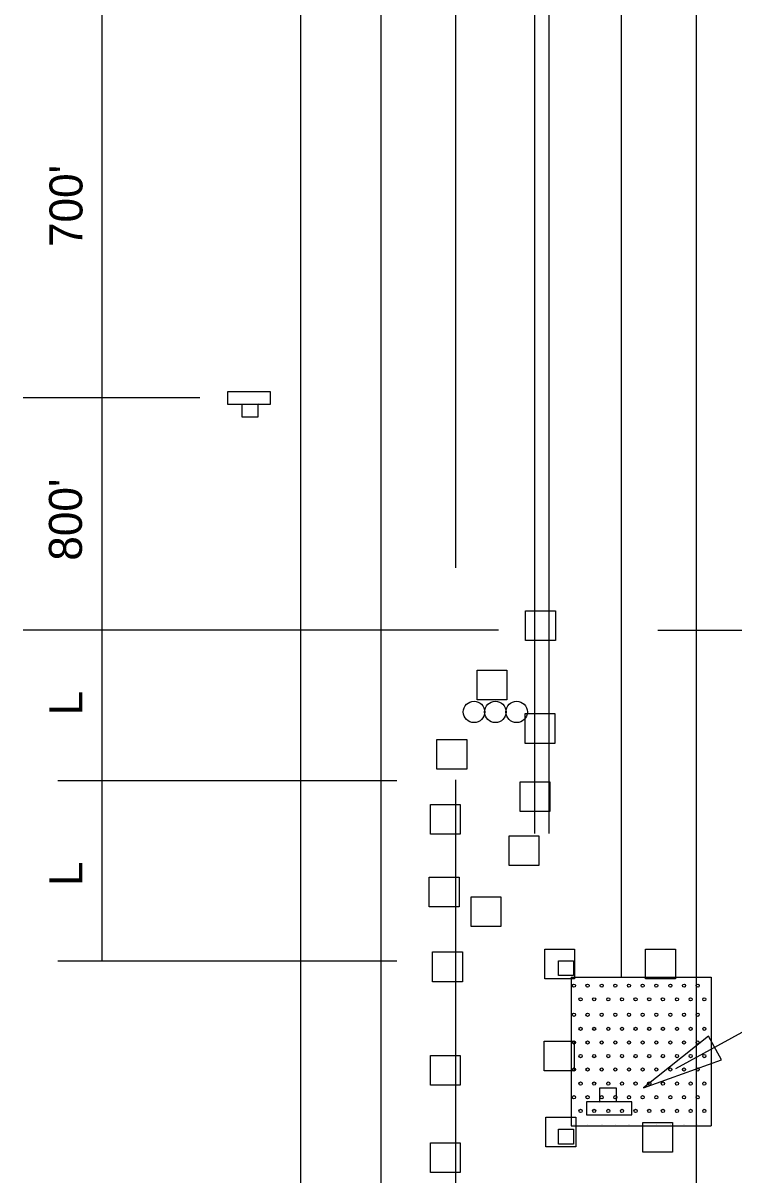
# Model space of a CAD drawing. Extents: x 15312.2 to 15319.5, y 15309 to 15319.2.
# Drawn here: x 15314.808 to 15316.1, y 15314.978 to 15317.071 of the extents above; entities that cross this region are included whole.
import ezdxf

# ---------------------------------------------------------------- set-up
doc = ezdxf.new("R2010")
doc.units = 0
for name, color, linetype in [('DETL-DIMS', 7, 'Continuous'), ('DETL-LINE', 7, 'Continuous'), ('DETL-NOTE', 7, 'Continuous'), ('USER-BORD', 7, 'Continuous')]:
    doc.layers.add(name, color=color, linetype=linetype)

# ---------------------------------------------------------------- blocks, each defined once
blk = doc.blocks.new('CD1')
at = {"layer": 'USER-BORD'}
blk.add_lwpolyline([(0, 0.031), (0.031, 0.031), (0.031, 0), (0, 0)], close=True, dxfattribs=at)
blk = doc.blocks.new('PANEL0')
at = {"layer": 'USER-BORD'}
for centre in [(0.0309, -0.0012), (0.0928, -0.0012), (0.1546, -0.0012)]:
    blk.add_circle(centre, 0.0312, dxfattribs=at)
blk = doc.blocks.new('SIGN13')
at = {"layer": 'USER-BORD'}
for points in [[(-0.013, 0.018), (0.011, 0.019), (0.011, 0.037), (-0.013, 0.037)], [(-0.031, 0.018), (-0.031, 0), (0.032, 0), (0.032, 0.018)]]:
    blk.add_lwpolyline(points, close=True, dxfattribs=at)

msp = doc.modelspace()

# ---------------------------------------------------------------- linework, layer by layer
at = {"layer": 'DETL-DIMS'}
for p, q in [((15314.952, 15316.7603), (15314.952, 15317.1273)), ((15314.952, 15316.3503), (15314.952, 15316.7603)), ((15315.129, 15316.39), (15314.808, 15316.39)), ((15314.952, 15315.9683), (15314.952, 15316.3503)), ((15315.672, 15315.968), (15314.808, 15315.968)), ((15314.952, 15315.3663), (15314.952, 15315.9683)), ((15315.961, 15315.968), (15316.476, 15315.968)), ((15315.487, 15315.694), (15314.871, 15315.694)), ((15315.994, 15315.171), (15316.454, 15315.425)), ((15315.487, 15315.366), (15314.871, 15315.366))]:
    msp.add_line(p, q, dxfattribs=at)
msp.add_lwpolyline([(15316.077, 15315.187), (15316.053, 15315.23), (15315.935, 15315.136)], close=True, dxfattribs=at)
at = {"layer": 'DETL-LINE'}
for p, q in [((15315.312, 15318.785), (15315.312, 15310.694)), ((15315.458, 15318.785), (15315.458, 15310.694)), ((15315.594, 15316.081), (15315.594, 15318.785)), ((15315.737, 15318.785), (15315.737, 15315.598)), ((15315.763, 15318.785), (15315.763, 15315.598)), ((15315.895, 15315.337), (15315.895, 15318.785)), ((15316.031, 15318.785), (15316.031, 15314.788)), ((15315.594, 15310.694), (15315.594, 15315.696)), ((15315.804, 15315.337), (15316.058, 15315.337)), ((15315.804, 15315.337), (15315.804, 15315.067)), ((15315.804, 15315.337), (15316.058, 15315.337)), ((15315.804, 15315.337), (15315.804, 15315.067)), ((15316.058, 15315.337), (15316.058, 15315.067)), ((15316.058, 15315.337), (15316.058, 15315.067)), ((15315.808, 15315.321), (15315.808, 15315.321)), ((15315.809, 15315.321), (15315.809, 15315.321)), ((15315.834, 15315.321), (15315.834, 15315.321)), ((15315.834, 15315.321), (15315.834, 15315.321)), ((15315.859, 15315.321), (15315.859, 15315.321)), ((15315.86, 15315.321), (15315.86, 15315.321)), ((15315.884, 15315.321), (15315.884, 15315.321)), ((15315.884, 15315.321), (15315.884, 15315.321)), ((15315.908, 15315.321), (15315.908, 15315.321)), ((15315.909, 15315.321), (15315.909, 15315.321)), ((15315.934, 15315.321), (15315.934, 15315.321)), ((15315.934, 15315.321), (15315.934, 15315.321)), ((15315.959, 15315.321), (15315.959, 15315.321)), ((15315.959, 15315.321), (15315.959, 15315.321)), ((15315.984, 15315.321), (15315.984, 15315.321)), ((15315.984, 15315.321), (15315.984, 15315.321)), ((15316.008, 15315.321), (15316.008, 15315.321)), ((15316.009, 15315.321), (15316.009, 15315.321)), ((15316.034, 15315.321), (15316.034, 15315.321)), ((15316.034, 15315.321), (15316.034, 15315.321)), ((15315.821, 15315.297), (15315.821, 15315.297)), ((15315.821, 15315.297), (15315.821, 15315.297)), ((15315.846, 15315.297), (15315.846, 15315.297)), ((15315.846, 15315.297), (15315.846, 15315.297)), ((15315.872, 15315.297), (15315.872, 15315.297)), ((15315.872, 15315.297), (15315.872, 15315.297)), ((15315.896, 15315.297), (15315.896, 15315.297)), ((15315.896, 15315.297), (15315.896, 15315.297)), ((15315.921, 15315.297), (15315.921, 15315.297)), ((15315.921, 15315.297), (15315.921, 15315.297)), ((15315.946, 15315.297), (15315.946, 15315.297)), ((15315.946, 15315.297), (15315.946, 15315.297)), ((15315.971, 15315.297), (15315.971, 15315.297)), ((15315.971, 15315.297), (15315.971, 15315.297)), ((15315.996, 15315.297), (15315.996, 15315.297)), ((15315.996, 15315.297), (15315.996, 15315.297)), ((15316.021, 15315.297), (15316.021, 15315.297)), ((15316.021, 15315.297), (15316.021, 15315.297)), ((15316.046, 15315.297), (15316.046, 15315.297)), ((15316.046, 15315.297), (15316.046, 15315.297)), ((15315.808, 15315.269), (15315.808, 15315.269)), ((15315.809, 15315.269), (15315.809, 15315.269)), ((15315.834, 15315.269), (15315.834, 15315.269)), ((15315.834, 15315.269), (15315.834, 15315.269)), ((15315.859, 15315.269), (15315.859, 15315.269)), ((15315.86, 15315.269), (15315.86, 15315.269)), ((15315.884, 15315.269), (15315.884, 15315.269)), ((15315.884, 15315.269), (15315.884, 15315.269)), ((15315.908, 15315.269), (15315.908, 15315.269)), ((15315.909, 15315.269), (15315.909, 15315.269)), ((15315.934, 15315.269), (15315.934, 15315.269)), ((15315.934, 15315.269), (15315.934, 15315.269)), ((15315.959, 15315.269), (15315.959, 15315.269)), ((15315.959, 15315.269), (15315.959, 15315.269)), ((15315.984, 15315.269), (15315.984, 15315.269)), ((15315.984, 15315.269), (15315.984, 15315.269)), ((15316.008, 15315.269), (15316.008, 15315.269)), ((15316.009, 15315.269), (15316.009, 15315.269)), ((15316.034, 15315.269), (15316.034, 15315.269)), ((15316.034, 15315.269), (15316.034, 15315.269)), ((15315.821, 15315.243), (15315.821, 15315.243)), ((15315.846, 15315.243), (15315.846, 15315.243)), ((15315.872, 15315.243), (15315.872, 15315.243)), ((15315.896, 15315.243), (15315.896, 15315.243)), ((15315.921, 15315.243), (15315.921, 15315.243)), ((15315.946, 15315.243), (15315.946, 15315.243)), ((15315.971, 15315.243), (15315.971, 15315.243)), ((15315.996, 15315.243), (15315.996, 15315.243)), ((15316.021, 15315.243), (15316.021, 15315.243)), ((15316.046, 15315.243), (15316.046, 15315.243)), ((15315.808, 15315.218), (15315.808, 15315.218)), ((15315.809, 15315.218), (15315.809, 15315.218)), ((15315.834, 15315.218), (15315.834, 15315.218)), ((15315.834, 15315.218), (15315.834, 15315.218)), ((15315.859, 15315.218), (15315.859, 15315.218)), ((15315.86, 15315.218), (15315.86, 15315.218)), ((15315.884, 15315.218), (15315.884, 15315.218)), ((15315.884, 15315.218), (15315.884, 15315.218)), ((15315.908, 15315.218), (15315.908, 15315.218)), ((15315.909, 15315.218), (15315.909, 15315.218)), ((15315.934, 15315.218), (15315.934, 15315.218)), ((15315.934, 15315.218), (15315.934, 15315.218)), ((15315.959, 15315.218), (15315.959, 15315.218)), ((15315.959, 15315.218), (15315.959, 15315.218)), ((15315.984, 15315.218), (15315.984, 15315.218)), ((15315.984, 15315.218), (15315.984, 15315.218)), ((15316.008, 15315.218), (15316.008, 15315.218)), ((15316.009, 15315.218), (15316.009, 15315.218)), ((15316.034, 15315.218), (15316.034, 15315.218)), ((15316.034, 15315.218), (15316.034, 15315.218)), ((15315.821, 15315.193), (15315.821, 15315.193)), ((15315.821, 15315.193), (15315.821, 15315.193)), ((15315.846, 15315.193), (15315.846, 15315.193)), ((15315.846, 15315.193), (15315.846, 15315.193)), ((15315.872, 15315.193), (15315.872, 15315.193)), ((15315.872, 15315.193), (15315.872, 15315.193)), ((15315.896, 15315.193), (15315.896, 15315.193)), ((15315.896, 15315.193), (15315.896, 15315.193)), ((15315.921, 15315.193), (15315.921, 15315.193)), ((15315.921, 15315.193), (15315.921, 15315.193)), ((15315.946, 15315.193), (15315.946, 15315.193)), ((15315.946, 15315.193), (15315.946, 15315.193)), ((15315.971, 15315.193), (15315.971, 15315.193)), ((15315.971, 15315.193), (15315.971, 15315.193)), ((15315.996, 15315.193), (15315.996, 15315.193)), ((15315.996, 15315.193), (15315.996, 15315.193)), ((15316.021, 15315.193), (15316.021, 15315.193)), ((15316.021, 15315.193), (15316.021, 15315.193)), ((15316.046, 15315.193), (15316.046, 15315.193)), ((15316.046, 15315.193), (15316.046, 15315.193)), ((15315.808, 15315.169), (15315.808, 15315.169)), ((15315.809, 15315.169), (15315.809, 15315.169)), ((15315.834, 15315.169), (15315.834, 15315.169)), ((15315.834, 15315.169), (15315.834, 15315.169)), ((15315.859, 15315.169), (15315.859, 15315.169)), ((15315.86, 15315.169), (15315.86, 15315.169)), ((15315.884, 15315.169), (15315.884, 15315.169)), ((15315.884, 15315.169), (15315.884, 15315.169)), ((15315.908, 15315.169), (15315.908, 15315.169)), ((15315.909, 15315.169), (15315.909, 15315.169)), ((15315.934, 15315.169), (15315.934, 15315.169)), ((15315.934, 15315.169), (15315.934, 15315.169)), ((15315.959, 15315.169), (15315.959, 15315.169)), ((15315.959, 15315.169), (15315.959, 15315.169)), ((15315.984, 15315.169), (15315.984, 15315.169)), ((15315.984, 15315.169), (15315.984, 15315.169)), ((15316.008, 15315.169), (15316.008, 15315.169)), ((15316.009, 15315.169), (15316.009, 15315.169)), ((15316.034, 15315.169), (15316.034, 15315.169)), ((15316.034, 15315.169), (15316.034, 15315.169)), ((15315.821, 15315.144), (15315.821, 15315.144)), ((15315.846, 15315.144), (15315.846, 15315.144)), ((15315.872, 15315.144), (15315.872, 15315.144)), ((15315.896, 15315.144), (15315.896, 15315.144)), ((15315.921, 15315.144), (15315.921, 15315.144)), ((15315.946, 15315.144), (15315.946, 15315.144)), ((15315.971, 15315.144), (15315.971, 15315.144)), ((15315.996, 15315.144), (15315.996, 15315.144)), ((15316.021, 15315.144), (15316.021, 15315.144)), ((15316.046, 15315.144), (15316.046, 15315.144)), ((15315.808, 15315.119), (15315.808, 15315.119)), ((15315.809, 15315.119), (15315.809, 15315.119)), ((15315.834, 15315.119), (15315.834, 15315.119)), ((15315.834, 15315.119), (15315.834, 15315.119)), ((15315.859, 15315.119), (15315.859, 15315.119)), ((15315.86, 15315.119), (15315.86, 15315.119)), ((15315.884, 15315.119), (15315.884, 15315.119)), ((15315.884, 15315.119), (15315.884, 15315.119)), ((15315.908, 15315.119), (15315.908, 15315.119)), ((15315.909, 15315.119), (15315.909, 15315.119)), ((15315.934, 15315.119), (15315.934, 15315.119)), ((15315.934, 15315.119), (15315.934, 15315.119)), ((15315.959, 15315.119), (15315.959, 15315.119)), ((15315.959, 15315.119), (15315.959, 15315.119)), ((15315.984, 15315.119), (15315.984, 15315.119)), ((15315.984, 15315.119), (15315.984, 15315.119)), ((15316.008, 15315.119), (15316.008, 15315.119)), ((15316.009, 15315.119), (15316.009, 15315.119)), ((15316.034, 15315.119), (15316.034, 15315.119)), ((15316.034, 15315.119), (15316.034, 15315.119)), ((15315.821, 15315.094), (15315.821, 15315.094)), ((15315.821, 15315.094), (15315.821, 15315.094)), ((15315.846, 15315.094), (15315.846, 15315.094)), ((15315.846, 15315.094), (15315.846, 15315.094)), ((15315.872, 15315.094), (15315.872, 15315.094)), ((15315.872, 15315.094), (15315.872, 15315.094)), ((15315.896, 15315.094), (15315.896, 15315.094)), ((15315.896, 15315.094), (15315.896, 15315.094)), ((15315.921, 15315.094), (15315.921, 15315.094)), ((15315.921, 15315.094), (15315.921, 15315.094)), ((15315.946, 15315.094), (15315.946, 15315.094)), ((15315.946, 15315.094), (15315.946, 15315.094)), ((15315.971, 15315.094), (15315.971, 15315.094)), ((15315.971, 15315.094), (15315.971, 15315.094)), ((15315.996, 15315.094), (15315.996, 15315.094)), ((15315.996, 15315.094), (15315.996, 15315.094)), ((15316.021, 15315.094), (15316.021, 15315.094)), ((15316.021, 15315.094), (15316.021, 15315.094)), ((15316.046, 15315.094), (15316.046, 15315.094)), ((15316.046, 15315.094), (15316.046, 15315.094)), ((15315.804, 15315.067), (15316.058, 15315.067)), ((15315.804, 15315.067), (15316.058, 15315.067)), ((15315.808, 15315.069), (15315.808, 15315.069)), ((15315.809, 15315.069), (15315.809, 15315.069)), ((15315.834, 15315.069), (15315.834, 15315.069)), ((15315.834, 15315.069), (15315.834, 15315.069)), ((15315.859, 15315.069), (15315.859, 15315.069)), ((15315.86, 15315.069), (15315.86, 15315.069)), ((15315.884, 15315.069), (15315.884, 15315.069)), ((15315.884, 15315.069), (15315.884, 15315.069)), ((15315.908, 15315.069), (15315.908, 15315.069)), ((15315.909, 15315.069), (15315.909, 15315.069)), ((15315.934, 15315.069), (15315.934, 15315.069)), ((15315.934, 15315.069), (15315.934, 15315.069)), ((15315.959, 15315.069), (15315.959, 15315.069)), ((15315.959, 15315.069), (15315.959, 15315.069)), ((15315.984, 15315.069), (15315.984, 15315.069)), ((15315.984, 15315.069), (15315.984, 15315.069)), ((15316.008, 15315.069), (15316.008, 15315.069)), ((15316.009, 15315.069), (15316.009, 15315.069)), ((15316.034, 15315.069), (15316.034, 15315.069)), ((15316.034, 15315.069), (15316.034, 15315.069))]:
    msp.add_line(p, q, dxfattribs=at)
for points in [[(15315.895, 15317.017), (15315.895, 15317.047)], [(15315.594, 15316.981), (15315.594, 15317.019)], [(15315.895, 15316.987), (15315.895, 15317.017)], [(15315.594, 15316.943), (15315.594, 15316.981)], [(15315.895, 15316.777), (15315.895, 15316.807)], [(15315.895, 15316.747), (15315.895, 15316.777)], [(15315.594, 15316.681), (15315.594, 15316.719)], [(15315.594, 15316.643), (15315.594, 15316.681)], [(15315.895, 15316.537), (15315.895, 15316.567)], [(15315.895, 15316.507), (15315.895, 15316.537)], [(15315.594, 15316.381), (15315.594, 15316.419)], [(15315.594, 15316.343), (15315.594, 15316.381)], [(15315.895, 15316.297), (15315.895, 15316.327)], [(15315.895, 15316.267), (15315.895, 15316.297)], [(15315.594, 15316.081), (15315.594, 15316.119)], [(15315.895, 15316.057), (15315.895, 15316.087)], [(15315.895, 15316.027), (15315.895, 15316.057)], [(15315.895, 15315.817), (15315.895, 15315.847)], [(15315.895, 15315.787), (15315.895, 15315.817)], [(15315.895, 15315.577), (15315.895, 15315.607)], [(15315.895, 15315.547), (15315.895, 15315.577)], [(15315.594, 15315.494), (15315.594, 15315.524)], [(15315.594, 15315.464), (15315.594, 15315.494)], [(15315.895, 15315.337), (15315.895, 15315.367)], [(15315.594, 15315.254), (15315.594, 15315.284)], [(15315.594, 15315.224), (15315.594, 15315.254)], [(15315.594, 15315.014), (15315.594, 15315.044)], [(15315.594, 15314.984), (15315.594, 15315.014)]]:
    msp.add_lwpolyline(points, dxfattribs=at)
for centre in [(15315.8088, 15315.3218), (15315.8336, 15315.3218), (15315.8592, 15315.3218), (15315.884, 15315.3218), (15315.9088, 15315.3218), (15315.9336, 15315.3218), (15315.9584, 15315.3218), (15315.984, 15315.3218), (15316.0088, 15315.3218), (15316.0336, 15315.3218), (15315.8208, 15315.297), (15315.8456, 15315.297), (15315.8712, 15315.297), (15315.896, 15315.297), (15315.9208, 15315.297), (15315.9456, 15315.297), (15315.9704, 15315.297), (15315.996, 15315.297), (15316.0208, 15315.297), (15316.0456, 15315.297), (15315.8088, 15315.2689), (15315.8336, 15315.2689), (15315.8592, 15315.2689), (15315.884, 15315.2689), (15315.9088, 15315.2689), (15315.9336, 15315.2689), (15315.9584, 15315.2689), (15315.984, 15315.2689), (15316.0088, 15315.2689), (15316.0336, 15315.2689), (15315.8208, 15315.2433), (15315.8456, 15315.2433), (15315.8712, 15315.2433), (15315.896, 15315.2433), (15315.9208, 15315.2433), (15315.9456, 15315.2433), (15315.9704, 15315.2433), (15315.996, 15315.2433), (15316.0208, 15315.2433), (15316.0456, 15315.2433), (15315.8088, 15315.2185), (15315.8336, 15315.2185), (15315.8592, 15315.2185), (15315.884, 15315.2185), (15315.9088, 15315.2185), (15315.9336, 15315.2185), (15315.9584, 15315.2185), (15315.984, 15315.2185), (15316.0088, 15315.2185), (15316.0336, 15315.2185), (15315.8208, 15315.1937), (15315.8456, 15315.1937), (15315.8712, 15315.1937), (15315.896, 15315.1937), (15315.9208, 15315.1937), (15315.9456, 15315.1937), (15315.9704, 15315.1937), (15315.996, 15315.1937), (15316.0208, 15315.1937), (15316.0456, 15315.1937), (15315.8088, 15315.1694), (15315.8336, 15315.1694), (15315.8592, 15315.1694), (15315.884, 15315.1694), (15315.9088, 15315.1694), (15315.9336, 15315.1694), (15315.9584, 15315.1694), (15315.984, 15315.1694), (15316.0088, 15315.1694), (15316.0336, 15315.1694), (15315.8208, 15315.1438), (15315.8456, 15315.1438), (15315.8712, 15315.1438), (15315.896, 15315.1438), (15315.9208, 15315.1438), (15315.9456, 15315.1438), (15315.9704, 15315.1438), (15315.996, 15315.1438), (15316.0208, 15315.1438), (15316.0456, 15315.1438), (15315.8088, 15315.119), (15315.8336, 15315.119), (15315.8592, 15315.119), (15315.884, 15315.119), (15315.9088, 15315.119), (15315.9336, 15315.119), (15315.9584, 15315.119), (15315.984, 15315.119), (15316.0088, 15315.119), (15316.0336, 15315.119), (15315.8208, 15315.0942), (15315.8456, 15315.0942), (15315.8712, 15315.0942), (15315.896, 15315.0942), (15315.9208, 15315.0942), (15315.9456, 15315.0942), (15315.9704, 15315.0942), (15315.996, 15315.0942), (15316.0208, 15315.0942), (15316.0456, 15315.0942)]:
    msp.add_circle(centre, 0.00291, dxfattribs=at)

# ---------------------------------------------------------------- block references
at = {"layer": 'DETL-LINE', "xscale": 1.236689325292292, "yscale": 1.236689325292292, "rotation": 180}
msp.add_blockref('SIGN13', (15315.219, 15316.401), dxfattribs=at)
at = {"layer": 'DETL-LINE'}
for name, p, xscale, yscale in [('CD1', (15315.721, 15315.949), 1.743723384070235, 1.743723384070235), ('CD1', (15315.633, 15315.841), 1.743723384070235, 1.743723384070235), ('PANEL0', (15315.608, 15315.82), 0.6251678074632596, 0.6251678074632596), ('CD1', (15315.72, 15315.762), 1.743723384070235, 1.743723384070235), ('CD1', (15315.56, 15315.715), 1.743723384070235, 1.743723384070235), ('CD1', (15315.711, 15315.638), 1.743723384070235, 1.743723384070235), ('CD1', (15315.548, 15315.597), 1.743723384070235, 1.743723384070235), ('CD1', (15315.691, 15315.54), 1.743723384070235, 1.743723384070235), ('CD1', (15315.546, 15315.465), 1.743723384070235, 1.743723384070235), ('CD1', (15315.622, 15315.429), 1.743723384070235, 1.743723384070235), ('CD1', (15315.552, 15315.329), 1.743723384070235, 1.743723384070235), ('CD1', (15315.756, 15315.334), 1.743723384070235, 1.743723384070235), ('CD1', (15315.939, 15315.334), 1.743723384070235, 1.743723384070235), ('CD1', (15315.781, 15315.34), 0.8718616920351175, 0.8718616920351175), ('CD1', (15315.755, 15315.167), 1.743723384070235, 1.743723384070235), ('CD1', (15315.548, 15315.141), 1.743723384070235, 1.743723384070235), ('SIGN13', (15315.872, 15315.087), 1.3077925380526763, 1.3077925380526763), ('CD1', (15315.758, 15315.029), 1.743723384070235, 1.743723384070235), ('CD1', (15315.781, 15315.034), 0.8718616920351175, 0.8718616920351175), ('CD1', (15315.934, 15315.019), 1.743723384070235, 1.743723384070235), ('CD1', (15315.548, 15314.982), 1.743723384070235, 1.743723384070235)]:
    msp.add_blockref(name, p, dxfattribs=dict(at, xscale=xscale, yscale=yscale))

# ---------------------------------------------------------------- texts
at = {"layer": 'DETL-NOTE'}
for s, p in [("700'", (15314.916, 15316.664)), ("800'", (15314.915, 15316.094)), ('L', (15314.916, 15315.813)), ('L', (15314.916, 15315.503))]:
    msp.add_text(s, height=0.06, rotation=90, dxfattribs=at).set_placement(p)

doc.saveas('drawing.dxf')
